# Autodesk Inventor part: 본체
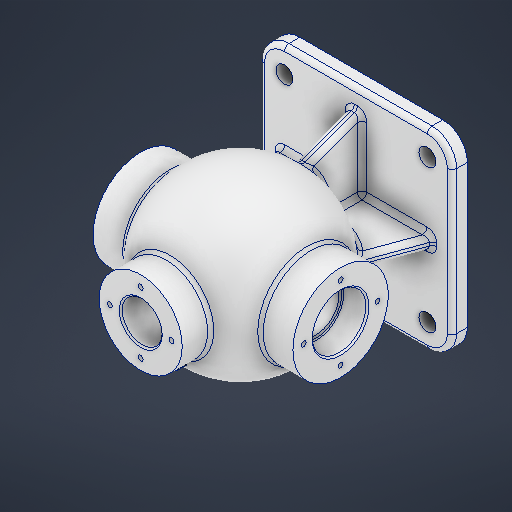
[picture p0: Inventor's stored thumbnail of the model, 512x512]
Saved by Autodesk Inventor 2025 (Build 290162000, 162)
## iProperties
Created: 2025-08
Part Number: 본체
Material: 알루미늄 6061
Document SubType Name: Modeling
Designer: infra11
Density: 2.7 g/cm^3
Appearance: 알루미늄 - 평지
Mass: 1519.11 g
Surface Area: 1171.84 cm^2
Volume: 562.634 cm^3
Author: infra11
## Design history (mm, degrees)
sketch "스케치1"
  geometry: L1 (62.5, -62.5)-(-62.5, -62.5); L2 (-62.5, -62.5)-(-62.5, 62.5); L3 (-62.5, 62.5)-(62.5, 62.5); L4 (62.5, 62.5)-(62.5, -62.5); L5 (62.5, -62.5)-(-62.5, 62.5); L6 (-62.5, -62.5)-(62.5, 62.5); 1 further point
  constraints: 12 end point, 2 midpoint, 2 parallel, 1 horizontal, 1 perpendicular
  dimensions: "d0" = 125 distance of L2.end L3.end; "d1" = 125 distance of L1.end L2.end
extrude "돌출1" new body sketch "스케치1" distance "d2" = 10; taper "d3" = 0 deg
sketch "스케치3"
  geometry: L1 (0, 139)-(0, 31); L2 (-62.5, 0)-(62.5, 0) reference; C1 r 44 at (0, 85); A1 r 54 centre (0, 85) between (0, 139) and (0, 31); 4 further points
  constraints: 2 centre point, 2 coincident, 2 end point, 2 point on circle, 1 midpoint, 1 vertical
  dimensions: "d4" = 85 distance from line of L2 point (0, 85); "d5" = 108 diameter of A1; "d6" = 62.5 distance from line of L2.end L1; "d22" = 88 diameter of C1
revolve "회전1" stored, may be unused: angle "d7" = 90 deg
sketch "스케치4"
  geometry: L1 (62.5, 10)-(-62.5, 10) reference; L2 (-50.5, 10)-(-33.792, 55.905); L3 (50.5, 10)-(33.792, 55.905); L4 (-62.5, 0)-(-62.5, 10) reference; L5 (62.5, 0)-(62.5, 10) reference; L6 (-33.792, 55.905)-(33.792, 55.905); 1 further point
  constraints: 6 end point, 2 point on line, 1 equal length
  dimensions: "d8" = 12 distance from line of L4 L2.start; "d9" = 12 distance from line of L5 L3.start; "d10" = 70 deg angle of L1 L2; "d11" = 70 deg angle of L1 L3; "d12" = 67.584 distance of L2.end L3.end
extrude "돌출2" join sketch "스케치4" stored distance "d13" = 8; taper "d14" = 0 deg
sketch "스케치5"
  geometry: L1 (-50.5, 10)-(-32.017, 60.783); L2 (62.5, 10)-(-62.5, 10) reference; L3 (50.5, 10)-(32.017, 60.783); L4 (-62.5, 0)-(-62.5, 10) reference; L5 (62.5, 0)-(62.5, 10) reference; L6 (-32.017, 60.783)-(-4, 60.783); L7 (-4, 60.783)-(-4, 46.186); L8 (32.017, 60.783)-(4, 60.783); L9 (4, 60.783)-(4, 46.186); 2 further points; 1 other entity
  constraints: 12 end point, 3 point on line, 2 perpendicular, 1 equal length, 1 horizontal, 1 other
  dimensions: "d15" = 12 distance from line of L4 L1.start; "d16" = 12 distance from line of L3.start L5; "d17" = 70 deg angle of L2 L1; "d18" = 70 deg angle of L2 L3; "d19" = 28.01666 distance of L1.end L6.end
extrude "돌출3" join sketch "스케치5" stored distance "d20" = 8; taper "d21" = 0 deg
sketch "스케치6"
  geometry: L1 (-65, 54)-(65, 54); L2 (65, 54)-(65, 116); L3 (65, 116)-(-65, 116); L4 (-65, 116)-(-65, 54); L5 (-65, 54)-(65, 116); L6 (65, 54)-(-65, 116); L7 (-62.5, 0)-(62.5, 0) reference; L8 (65, 85)-(-65, 85); L9 (65, 85)-(49, 85); L10 (49, 85)-(49, 102.5); L11 (49, 102.5)-(65, 102.5); L12 (65, 102.5)-(65, 85); L13 (27, 150)-(-27, 150); L14 (-27, 150)-(-27, 131.765); L15 (-27, 131.765)-(27, 131.765); L16 (27, 131.765)-(27, 150); L17 (0, 150)-(0, 131.765); L18 (-49, 102.5)-(-65, 102.5); L19 (-49, 85)-(-49, 102.5); A1 r 54 centre (0, 85) between (37.385, 46.034) and (-37.385, 46.034) reference; 15 further points
  constraints: 36 end point, 6 midpoint, 6 parallel, 3 horizontal, 3 perpendicular, 3 symmetric about line, 2 point on circle, 2 vertical alignment, 1 vertical
  dimensions: "d23" = 130 distance of L3.end L2.end; "d24" = 62 distance of L2.end L1.end; "d25" = 85 distance from line of L7 point (0, 85); "d26" = 16 distance of L10.end L11.end; "d27" = 17.5 distance of L9.end L10.end; "d28" = 150 distance between parallel lines of L7 L13; "d29" = 54 distance between parallel lines of L14 L16
revolve "회전2" stored, may be unused: angle "d30" = 90 deg
revolve "회전3" stored, may be unused: angle "d31" = 90 deg
sketch "스케치7"
  geometry: C1 r 17.5 at (0, 0) reference; 2 further points
  constraints: 1 coincident
hole "구멍1" sketch "스케치7" at (0, 0) diameter "d32" = 30; stored, may be unused: countersink angle "d36" = 90 deg, drill point angle "d38" = 0 deg; dims "d33" = 12, "d34" = 10, "d35" = 1, "d37" = 17.1
sketch "스케치8"
  geometry: 2 further points
  constraints: 1 coincident
hole "구멍2" sketch "스케치8" at (0, 0) diameter "d39" = 26; stored, may be unused: countersink angle "d43" = 90 deg, drill point angle "d45" = 0 deg; dims "d40" = 6, "d41" = 4, "d42" = 2, "d44" = 8
revolve "회전4" stored, may be unused: angle "d46" = 90 deg
sketch "스케치9"
  geometry: L1 (-37.329, -4)-(-4, -4) reference; A1 r 20 centre (0, 0) between (0, -20) and (-20, 0); 2 further points
  constraints: 4 point on circle, 1 centre point
  dimensions: "d100" = 40 diameter of A1; "d101" = 4 distance from line of point (20, 0) L1; "d102" = 24 distance from line of point (0, 20) L1; "d103" = 4 distance from line of A1.centre L1; "d104" = 16 distance from line of A1.start L1; "d105" = 4 distance from line of A1.end L1; "d106" = 24.33105 distance of L1.end point (20, 0)
hole "구멍3" sketch "스케치9" at (0, -20), (-20, 0), (0, 20), (20, 0) diameter "d51" = 3.242; stored, may be unused: countersink angle "d55" = 90 deg, drill point angle "d57" = 118 deg; dims "d52" = 9, "d53" = 4, "d54" = 2, "d56" = 11
sketch "스케치10"
  geometry: L1 (85, -62.5)-(85, 62.5) reference; A1 r 24 centre (0, 0) between (0, -24) and (-24, 0); 3 further points
  constraints: 4 point on circle, 3 horizontal alignment, 2 vertical alignment, 1 centre point
  dimensions: "d58" = 48 diameter of A1; "d59" = 85 distance from line of L1 A1.centre
hole "구멍4" sketch "스케치10" at (0, -24), (-24, 0), (0, 24), (24, 0) diameter "d60" = 3.242; stored, may be unused: countersink angle "d64" = 90 deg, drill point angle "d66" = 118 deg; dims "d61" = 12, "d62" = 4, "d63" = 2, "d65" = 15
node "작업 평면1"
sketch "스케치11" dims "d0" = 125, "d1" = 125
  geometry: L1 (-20.739, 144.002)-(20.739, 144.002); L2 (20.739, 144.002)-(20.739, 137.998); L3 (20.739, 137.998)-(-20.739, 137.998); L4 (-20.739, 137.998)-(-20.739, 144.002); L5 (-62.5, 10)-(62.5, 10) reference; L6 (-27, 150)-(27, 150) reference; 4 further points
  constraints: 3 midpoint, 1 vertical alignment, 2 other
  dimensions: "d68" = 9 distance from line of point (-20.739, 141) L6
feature "엠보싱1" sketch "스케치11" dims "d0" = 125, "d1" = 125, "d69" = 0.5, "d70" = 0
sketch "스케치12"
  geometry: L1 (46.5, -46.5)-(-46.5, -46.5); L2 (-46.5, -46.5)-(-46.5, 46.5); L3 (-46.5, 46.5)-(46.5, 46.5); L4 (46.5, 46.5)-(46.5, -46.5); L5 (46.5, -46.5)-(-46.5, 46.5); L6 (-46.5, -46.5)-(46.5, 46.5); 1 further point
  constraints: 12 end point, 2 midpoint, 2 parallel, 1 horizontal, 1 perpendicular
  dimensions: "d71" = 93 distance of L2.end L3.end; "d72" = 93 distance of L1.end L2.end
hole "구멍5" sketch "스케치12" at (-46.5, -46.5), (46.5, -46.5), (-46.5, 46.5), (46.5, 46.5) diameter "d73" = 11; stored, may be unused: countersink angle "d77" = 90 deg, drill point angle "d79" = 0 deg; dims "d74" = 12, "d75" = 4, "d76" = 2, "d78" = 15
fillet "모깎기1" dims "d80" = 3
fillet "모깎기2" dims "d81" = 3
fillet "모깎기3" dims "d82" = 3
fillet "모깎기4" dims "d83" = 16
fillet "모깎기5" dims "d84" = 3
chamfer "모따기1" distance "d85" = 1; stored, may be unused: second distance "d86" = 2, angle "d87" = 45 deg
chamfer "모따기2" distance "d88" = 1; stored, may be unused: second distance "d89" = 2, angle "d90" = 45 deg
chamfer "모따기5" distance "d97" = 1; stored, may be unused: second distance "d98" = 2, angle "d99" = 45 deg
revolve "회전5" stored, may be unused: angle "d107" = 90 deg
fillet "모깎기6" dims "d114" = 0.6
fillet "모깎기7" dims "d115" = 0.6
feature "Ϊ耀ά耀ή耀ΰ耀β耀δ耀ζ耀θ耀" dims "d0" = 125, "d1" = 125, "d2" = 10, "d3" = 0, "d4" = 85, "d5" = 108, "d6" = 62.5, "d7" = 90 deg, "d8" = 12, "d9" = 12, "d10" = 70 deg, "d11" = 70 deg, "d12" = 67.584, "d13" = 8, "d14" = 0, "d15" = 12, "d16" = 12, "d17" = 70 deg, "d18" = 70 deg, "d19" = 28.01666, "d20" = 8, "d21" = 0, "d22" = 88, "d23" = 130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
node "솔리드1"
mirror "미러1"
feature "A9D066F2-1C7D-4E18-AEED-F7BC21143FA4" dims "d32" = 30, "d33" = 12, "d34" = 10, "d35" = 1, "d36" = 90 deg, "d37" = 17.1, "d38" = 0
